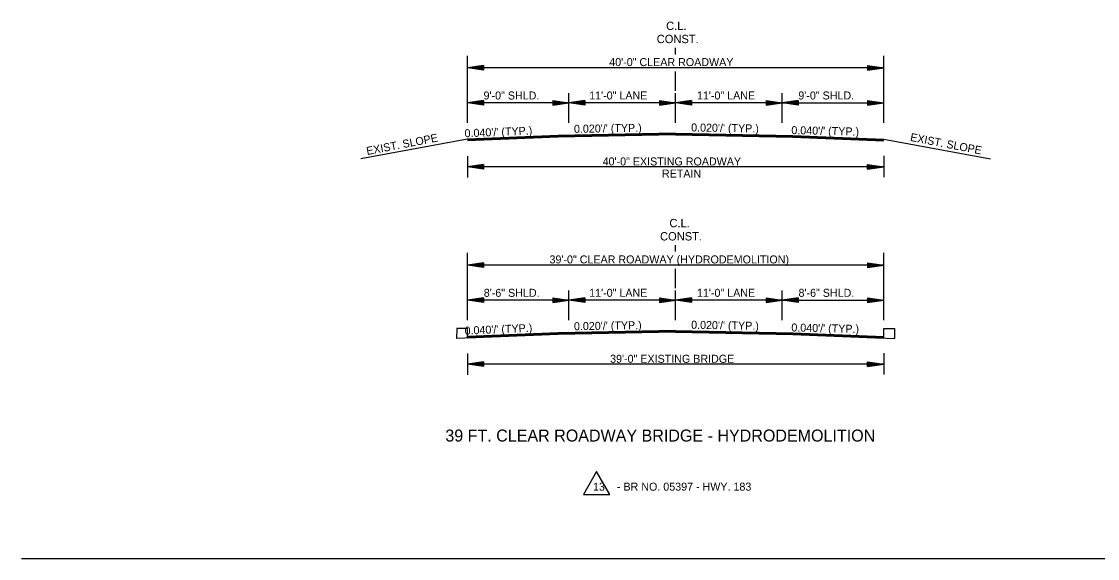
# Model space of a CAD drawing. Extents: x 549600 to 1930787, y -1955432 to 596640.
# Drawn here: x 551009 to 552017, y -1951238 to -1950735 of the extents above; entities that cross this region are included whole.
import ezdxf

# ---------------------------------------------------------------- set-up
doc = ezdxf.new("R2010")
doc.units = 0
doc.layers.add('R_Border', color=7, linetype='Continuous')
doc.layers.add('S_AREA_CALC', color=7, linetype='Continuous')

msp = doc.modelspace()

# ---------------------------------------------------------------- linework, layer by layer
at = {"layer": 'R_Border'}
for p, q in [((551512, -1950841.6), (551427, -1950845)), ((551512, -1950841.9), (551427, -1950845.3)), ((551512, -1950842.2), (551427, -1950845.6)), ((551512, -1950842.5), (551427, -1950845.9)), ((551512, -1950842.8), (551427, -1950846.2)), ((551512, -1950843.1), (551427, -1950846.5)), ((551512, -1950843.3), (551427, -1950846.7)), ((551732, -1950841.6), (551817, -1950845)), ((551732, -1950841.9), (551817, -1950845.3)), ((551732, -1950842.2), (551817, -1950845.6)), ((551732, -1950842.5), (551817, -1950845.9)), ((551732, -1950842.8), (551817, -1950846.2)), ((551732, -1950843.1), (551817, -1950846.5)), ((551732, -1950843.3), (551817, -1950846.7)), ((551416.9, -1951022.6), (551416.8, -1951031.9)), ((551512, -1951028.1), (551416.8, -1951031.9)), ((551427, -1951022.6), (551416.9, -1951022.6)), ((551427, -1951031.4), (551427, -1951022.6)), ((551512, -1951026.5), (551427, -1951029.9)), ((551512, -1951026.8), (551427, -1951030.2)), ((551512, -1951027.1), (551427, -1951030.5)), ((551512, -1951027.4), (551427, -1951030.8)), ((551512, -1951027.7), (551427, -1951031.1)), ((551512, -1951028), (551427, -1951031.4)), ((551732, -1951026.5), (551817, -1951029.9)), ((551732, -1951026.8), (551817, -1951030.2)), ((551732, -1951027.1), (551817, -1951030.5)), ((551732, -1951027.4), (551817, -1951030.8)), ((551732, -1951027.7), (551817, -1951031.1)), ((551732, -1951028), (551817, -1951031.4)), ((551732, -1951028.1), (551827.2, -1951031.9)), ((551817, -1951022.6), (551827.2, -1951022.6)), ((551817, -1951031.4), (551817, -1951022.6)), ((551827.2, -1951022.6), (551827.2, -1951031.9)), ((551535.6, -1951177.9), (551560.4, -1951177.9)), ((551009, -1951237.9), (552070.2, -1951237.9))]:
    msp.add_line(p, q, dxfattribs=at)
msp.add_lwpolyline([(551560.4, -1951177.9), (551548, -1951156.4), (551535.6, -1951177.9)], dxfattribs=at)
at = {"layer": 'S_AREA_CALC'}
for p, q in [((551622, -1950765.6), (551622, -1950759.4)), ((551427, -1950829.8), (551427, -1950766.9)), ((551817, -1950829.8), (551817, -1950766.9)), ((551442, -1950776), (551427, -1950778.2)), ((551817, -1950778.2), (551427, -1950778.2)), ((551442, -1950780.5), (551427, -1950778.2)), ((551442, -1950776.4), (551429.5, -1950778.2)), ((551442, -1950780.1), (551429.5, -1950778.2)), ((551442, -1950776.8), (551432.1, -1950778.2)), ((551442, -1950779.7), (551432.1, -1950778.2)), ((551442, -1950777.1), (551434.6, -1950778.2)), ((551442, -1950779.4), (551434.6, -1950778.2)), ((551442, -1950777.5), (551437.1, -1950778.2)), ((551442, -1950779), (551437.1, -1950778.2)), ((551442, -1950777.9), (551439.6, -1950778.2)), ((551442, -1950778.6), (551439.6, -1950778.2)), ((551442, -1950776), (551442, -1950780.5)), ((551802, -1950776), (551817, -1950778.2)), ((551802, -1950776), (551802, -1950780.5)), ((551802, -1950776.4), (551814.5, -1950778.2)), ((551802, -1950776.8), (551811.9, -1950778.2)), ((551802, -1950777.1), (551809.4, -1950778.2)), ((551802, -1950777.5), (551806.9, -1950778.2)), ((551802, -1950777.9), (551804.4, -1950778.2)), ((551802, -1950780.5), (551817, -1950778.2)), ((551802, -1950779), (551806.9, -1950778.2)), ((551802, -1950779.7), (551811.9, -1950778.2)), ((551802, -1950780.1), (551814.5, -1950778.2)), ((551802, -1950779.4), (551809.4, -1950778.2)), ((551802, -1950778.6), (551804.4, -1950778.2)), ((551622, -1950789.9), (551622, -1950781.6)), ((551622, -1950799.8), (551622, -1950789.9)), ((551442, -1950808.8), (551427, -1950811.1)), ((551442, -1950809.2), (551429.5, -1950811.1)), ((551442, -1950809.6), (551432.1, -1950811.1)), ((551442, -1950808.8), (551442, -1950813.3)), ((551507, -1950808.8), (551522, -1950811.1)), ((551507, -1950808.8), (551507, -1950813.3)), ((551507, -1950809.2), (551519.5, -1950811.1)), ((551507, -1950809.6), (551516.9, -1950811.1)), ((551522, -1950829.8), (551522, -1950801.9)), ((551537, -1950808.8), (551522, -1950811.1)), ((551537, -1950809.2), (551524.5, -1950811.1)), ((551537, -1950809.6), (551527.1, -1950811.1)), ((551537, -1950808.8), (551537, -1950813.3)), ((551607, -1950808.8), (551622, -1950811.1)), ((551607, -1950808.8), (551607, -1950813.3)), ((551607, -1950809.2), (551619.5, -1950811.1)), ((551607, -1950809.6), (551616.9, -1950811.1)), ((551622, -1950829.8), (551622, -1950801.9)), ((551637, -1950808.8), (551622, -1950811.1)), ((551637, -1950809.2), (551624.5, -1950811.1)), ((551637, -1950809.6), (551627.1, -1950811.1)), ((551637, -1950808.8), (551637, -1950813.3)), ((551707, -1950808.8), (551722, -1950811.1)), ((551707, -1950808.8), (551707, -1950813.3)), ((551707, -1950809.2), (551719.5, -1950811.1)), ((551707, -1950809.6), (551716.9, -1950811.1)), ((551722, -1950829.8), (551722, -1950801.9)), ((551737, -1950808.8), (551722, -1950811.1)), ((551737, -1950809.2), (551724.5, -1950811.1)), ((551737, -1950809.6), (551727.1, -1950811.1)), ((551737, -1950808.8), (551737, -1950813.3)), ((551802, -1950808.8), (551817, -1950811.1)), ((551802, -1950808.8), (551802, -1950813.3)), ((551802, -1950809.2), (551814.5, -1950811.1)), ((551802, -1950809.6), (551811.9, -1950811.1)), ((551522, -1950811.1), (551427, -1950811.1)), ((551442, -1950813.3), (551427, -1950811.1)), ((551442, -1950813), (551429.5, -1950811.1)), ((551442, -1950812.6), (551432.1, -1950811.1)), ((551442, -1950810), (551434.6, -1950811.1)), ((551442, -1950812.2), (551434.6, -1950811.1)), ((551442, -1950810.3), (551437.1, -1950811.1)), ((551442, -1950811.8), (551437.1, -1950811.1)), ((551442, -1950810.7), (551439.6, -1950811.1)), ((551442, -1950811.4), (551439.6, -1950811.1)), ((551507, -1950810), (551514.4, -1950811.1)), ((551507, -1950810.3), (551511.9, -1950811.1)), ((551507, -1950810.7), (551509.4, -1950811.1)), ((551507, -1950813.3), (551522, -1950811.1)), ((551507, -1950811.8), (551511.9, -1950811.1)), ((551507, -1950812.6), (551516.9, -1950811.1)), ((551507, -1950813), (551519.5, -1950811.1)), ((551507, -1950812.2), (551514.4, -1950811.1)), ((551507, -1950811.4), (551509.4, -1950811.1)), ((551622, -1950811.1), (551522, -1950811.1)), ((551537, -1950813.3), (551522, -1950811.1)), ((551537, -1950813), (551524.5, -1950811.1)), ((551537, -1950812.6), (551527.1, -1950811.1)), ((551537, -1950810), (551529.6, -1950811.1)), ((551537, -1950812.2), (551529.6, -1950811.1)), ((551537, -1950810.3), (551532.1, -1950811.1)), ((551537, -1950811.8), (551532.1, -1950811.1)), ((551537, -1950810.7), (551534.6, -1950811.1)), ((551537, -1950811.4), (551534.6, -1950811.1)), ((551607, -1950810), (551614.4, -1950811.1)), ((551607, -1950810.3), (551611.9, -1950811.1)), ((551607, -1950810.7), (551609.4, -1950811.1)), ((551607, -1950813.3), (551622, -1950811.1)), ((551607, -1950811.8), (551611.9, -1950811.1)), ((551607, -1950812.6), (551616.9, -1950811.1)), ((551607, -1950813), (551619.5, -1950811.1)), ((551607, -1950812.2), (551614.4, -1950811.1)), ((551607, -1950811.4), (551609.4, -1950811.1)), ((551722, -1950811.1), (551622, -1950811.1)), ((551637, -1950813.3), (551622, -1950811.1)), ((551637, -1950813), (551624.5, -1950811.1)), ((551637, -1950812.6), (551627.1, -1950811.1)), ((551637, -1950810), (551629.6, -1950811.1)), ((551637, -1950812.2), (551629.6, -1950811.1)), ((551637, -1950810.3), (551632.1, -1950811.1)), ((551637, -1950811.8), (551632.1, -1950811.1)), ((551637, -1950810.7), (551634.6, -1950811.1)), ((551637, -1950811.4), (551634.6, -1950811.1)), ((551707, -1950810), (551714.4, -1950811.1)), ((551707, -1950810.3), (551711.9, -1950811.1)), ((551707, -1950810.7), (551709.4, -1950811.1)), ((551707, -1950813.3), (551722, -1950811.1)), ((551707, -1950811.8), (551711.9, -1950811.1)), ((551707, -1950812.6), (551716.9, -1950811.1)), ((551707, -1950813), (551719.5, -1950811.1)), ((551707, -1950812.2), (551714.4, -1950811.1)), ((551707, -1950811.4), (551709.4, -1950811.1)), ((551722, -1950811.1), (551817, -1950811.1)), ((551737, -1950813.3), (551722, -1950811.1)), ((551737, -1950813), (551724.5, -1950811.1)), ((551737, -1950812.6), (551727.1, -1950811.1)), ((551737, -1950810), (551729.6, -1950811.1)), ((551737, -1950812.2), (551729.6, -1950811.1)), ((551737, -1950810.3), (551732.1, -1950811.1)), ((551737, -1950811.8), (551732.1, -1950811.1)), ((551737, -1950810.7), (551734.6, -1950811.1)), ((551737, -1950811.4), (551734.6, -1950811.1)), ((551802, -1950810), (551809.4, -1950811.1)), ((551802, -1950810.3), (551806.9, -1950811.1)), ((551802, -1950810.7), (551804.4, -1950811.1)), ((551802, -1950813.3), (551817, -1950811.1)), ((551802, -1950811.8), (551806.9, -1950811.1)), ((551802, -1950812.6), (551811.9, -1950811.1)), ((551802, -1950813), (551814.5, -1950811.1)), ((551802, -1950812.2), (551809.4, -1950811.1)), ((551802, -1950811.4), (551804.4, -1950811.1)), ((551622, -1950839.4), (551512, -1950841.6)), ((551622, -1950839.7), (551512, -1950841.9)), ((551622, -1950840), (551512, -1950842.2)), ((551622, -1950839.4), (551732, -1950841.6)), ((551622, -1950839.7), (551732, -1950841.9)), ((551622, -1950840), (551732, -1950842.2)), ((551427, -1950845), (551326.9, -1950863.4)), ((551622, -1950840.3), (551512, -1950842.5)), ((551622, -1950840.6), (551512, -1950842.8)), ((551622, -1950840.9), (551512, -1950843.1)), ((551622, -1950841.1), (551512, -1950843.3)), ((551622, -1950840.3), (551732, -1950842.5)), ((551622, -1950840.6), (551732, -1950842.8)), ((551622, -1950840.9), (551732, -1950843.1)), ((551622, -1950841.1), (551732, -1950843.3)), ((551817, -1950845), (551917.1, -1950863.4)), ((551427, -1950861), (551427, -1950881)), ((551442, -1950868.8), (551427, -1950871)), ((551442, -1950869.2), (551429.5, -1950871)), ((551442, -1950869.6), (551432.1, -1950871)), ((551442, -1950869.9), (551434.6, -1950871)), ((551442, -1950870.3), (551437.1, -1950871)), ((551442, -1950868.8), (551442, -1950873.3)), ((551802, -1950868.8), (551817, -1950871)), ((551802, -1950873.3), (551802, -1950868.8)), ((551802, -1950869.2), (551814.5, -1950871)), ((551802, -1950869.6), (551811.9, -1950871)), ((551802, -1950869.9), (551809.4, -1950871)), ((551802, -1950870.3), (551806.9, -1950871)), ((551817, -1950860.8), (551817, -1950880.8)), ((551442, -1950873.3), (551427, -1950871)), ((551817, -1950871), (551427, -1950871)), ((551442, -1950872.9), (551429.5, -1950871)), ((551442, -1950872.5), (551432.1, -1950871)), ((551442, -1950872.2), (551434.6, -1950871)), ((551442, -1950871.8), (551437.1, -1950871)), ((551442, -1950870.7), (551439.6, -1950871)), ((551442, -1950871.4), (551439.6, -1950871)), ((551802, -1950870.7), (551804.4, -1950871)), ((551802, -1950873.3), (551817, -1950871)), ((551802, -1950871.8), (551806.9, -1950871)), ((551802, -1950872.5), (551811.9, -1950871)), ((551802, -1950872.9), (551814.5, -1950871)), ((551802, -1950872.2), (551809.4, -1950871)), ((551802, -1950871.4), (551804.4, -1950871)), ((551622, -1950950.4), (551622, -1950944.3)), ((551427, -1951014.7), (551427, -1950951.7)), ((551442, -1950960.9), (551427, -1950963.1)), ((551442, -1950960.9), (551442, -1950965.4)), ((551802, -1950960.9), (551817, -1950963.1)), ((551802, -1950960.9), (551802, -1950965.4)), ((551817, -1951014.7), (551817, -1950951.7)), ((551817, -1950963.1), (551427, -1950963.1)), ((551442, -1950965.4), (551427, -1950963.1)), ((551442, -1950961.3), (551429.5, -1950963.1)), ((551442, -1950965), (551429.5, -1950963.1)), ((551442, -1950961.6), (551432.1, -1950963.1)), ((551442, -1950964.6), (551432.1, -1950963.1)), ((551442, -1950962), (551434.6, -1950963.1)), ((551442, -1950964.2), (551434.6, -1950963.1)), ((551442, -1950962.4), (551437.1, -1950963.1)), ((551442, -1950963.9), (551437.1, -1950963.1)), ((551442, -1950962.8), (551439.6, -1950963.1)), ((551442, -1950963.5), (551439.6, -1950963.1)), ((551622, -1950974.8), (551622, -1950966.5)), ((551802, -1950961.3), (551814.5, -1950963.1)), ((551802, -1950961.6), (551811.9, -1950963.1)), ((551802, -1950962), (551809.4, -1950963.1)), ((551802, -1950962.4), (551806.9, -1950963.1)), ((551802, -1950962.8), (551804.4, -1950963.1)), ((551802, -1950965.4), (551817, -1950963.1)), ((551802, -1950963.9), (551806.9, -1950963.1)), ((551802, -1950964.6), (551811.9, -1950963.1)), ((551802, -1950965), (551814.5, -1950963.1)), ((551802, -1950964.2), (551809.4, -1950963.1)), ((551802, -1950963.5), (551804.4, -1950963.1)), ((551622, -1950984.6), (551622, -1950974.8)), ((551522, -1951014.7), (551522, -1950986.8)), ((551622, -1951014.7), (551622, -1950986.8)), ((551722, -1951014.7), (551722, -1950986.8)), ((551442, -1950993.7), (551427, -1950996)), ((551522, -1950996), (551427, -1950996)), ((551442, -1950998.2), (551427, -1950996)), ((551442, -1950994.1), (551429.5, -1950996)), ((551442, -1950997.8), (551429.5, -1950996)), ((551442, -1950994.5), (551432.1, -1950996)), ((551442, -1950997.5), (551432.1, -1950996)), ((551442, -1950994.8), (551434.6, -1950996)), ((551442, -1950997.1), (551434.6, -1950996)), ((551442, -1950995.2), (551437.1, -1950996)), ((551442, -1950996.7), (551437.1, -1950996)), ((551442, -1950995.6), (551439.6, -1950996)), ((551442, -1950996.3), (551439.6, -1950996)), ((551442, -1950993.7), (551442, -1950998.2)), ((551507, -1950993.7), (551522, -1950996)), ((551507, -1950993.7), (551507, -1950998.2)), ((551507, -1950994.1), (551519.5, -1950996)), ((551507, -1950994.5), (551516.9, -1950996)), ((551507, -1950994.8), (551514.4, -1950996)), ((551507, -1950995.2), (551511.9, -1950996)), ((551507, -1950995.6), (551509.4, -1950996)), ((551507, -1950998.2), (551522, -1950996)), ((551507, -1950996.7), (551511.9, -1950996)), ((551507, -1950997.5), (551516.9, -1950996)), ((551507, -1950997.8), (551519.5, -1950996)), ((551507, -1950997.1), (551514.4, -1950996)), ((551507, -1950996.3), (551509.4, -1950996)), ((551537, -1950993.7), (551522, -1950996)), ((551622, -1950996), (551522, -1950996)), ((551537, -1950998.2), (551522, -1950996)), ((551537, -1950994.1), (551524.5, -1950996)), ((551537, -1950997.8), (551524.5, -1950996)), ((551537, -1950994.5), (551527.1, -1950996)), ((551537, -1950997.5), (551527.1, -1950996)), ((551537, -1950994.8), (551529.6, -1950996)), ((551537, -1950997.1), (551529.6, -1950996)), ((551537, -1950995.2), (551532.1, -1950996)), ((551537, -1950996.7), (551532.1, -1950996)), ((551537, -1950995.6), (551534.6, -1950996)), ((551537, -1950996.3), (551534.6, -1950996)), ((551537, -1950993.7), (551537, -1950998.2)), ((551607, -1950993.7), (551622, -1950996)), ((551607, -1950993.7), (551607, -1950998.2)), ((551607, -1950994.1), (551619.5, -1950996)), ((551607, -1950994.5), (551616.9, -1950996)), ((551607, -1950994.8), (551614.4, -1950996)), ((551607, -1950995.2), (551611.9, -1950996)), ((551607, -1950995.6), (551609.4, -1950996)), ((551607, -1950998.2), (551622, -1950996)), ((551607, -1950996.7), (551611.9, -1950996)), ((551607, -1950997.5), (551616.9, -1950996)), ((551607, -1950997.8), (551619.5, -1950996)), ((551607, -1950997.1), (551614.4, -1950996)), ((551607, -1950996.3), (551609.4, -1950996)), ((551637, -1950993.7), (551622, -1950996)), ((551722, -1950996), (551622, -1950996)), ((551637, -1950998.2), (551622, -1950996)), ((551637, -1950994.1), (551624.5, -1950996)), ((551637, -1950997.8), (551624.5, -1950996)), ((551637, -1950994.5), (551627.1, -1950996)), ((551637, -1950997.5), (551627.1, -1950996)), ((551637, -1950994.8), (551629.6, -1950996)), ((551637, -1950997.1), (551629.6, -1950996)), ((551637, -1950995.2), (551632.1, -1950996)), ((551637, -1950996.7), (551632.1, -1950996)), ((551637, -1950995.6), (551634.6, -1950996)), ((551637, -1950996.3), (551634.6, -1950996)), ((551637, -1950993.7), (551637, -1950998.2)), ((551707, -1950993.7), (551722, -1950996)), ((551707, -1950993.7), (551707, -1950998.2)), ((551707, -1950994.1), (551719.5, -1950996)), ((551707, -1950994.5), (551716.9, -1950996)), ((551707, -1950994.8), (551714.4, -1950996)), ((551707, -1950995.2), (551711.9, -1950996)), ((551707, -1950995.6), (551709.4, -1950996)), ((551707, -1950998.2), (551722, -1950996)), ((551707, -1950996.7), (551711.9, -1950996)), ((551707, -1950997.5), (551716.9, -1950996)), ((551707, -1950997.8), (551719.5, -1950996)), ((551707, -1950997.1), (551714.4, -1950996)), ((551707, -1950996.3), (551709.4, -1950996)), ((551737, -1950993.7), (551722, -1950996)), ((551722, -1950996), (551817, -1950996)), ((551737, -1950998.2), (551722, -1950996)), ((551737, -1950994.1), (551724.5, -1950996)), ((551737, -1950997.8), (551724.5, -1950996)), ((551737, -1950994.5), (551727.1, -1950996)), ((551737, -1950997.5), (551727.1, -1950996)), ((551737, -1950994.8), (551729.6, -1950996)), ((551737, -1950997.1), (551729.6, -1950996)), ((551737, -1950995.2), (551732.1, -1950996)), ((551737, -1950996.7), (551732.1, -1950996)), ((551737, -1950995.6), (551734.6, -1950996)), ((551737, -1950996.3), (551734.6, -1950996)), ((551737, -1950993.7), (551737, -1950998.2)), ((551802, -1950993.7), (551817, -1950996)), ((551802, -1950993.7), (551802, -1950998.2)), ((551802, -1950994.1), (551814.5, -1950996)), ((551802, -1950994.5), (551811.9, -1950996)), ((551802, -1950994.8), (551809.4, -1950996)), ((551802, -1950995.2), (551806.9, -1950996)), ((551802, -1950995.6), (551804.4, -1950996)), ((551802, -1950998.2), (551817, -1950996)), ((551802, -1950996.7), (551806.9, -1950996)), ((551802, -1950997.5), (551811.9, -1950996)), ((551802, -1950997.8), (551814.5, -1950996)), ((551802, -1950997.1), (551809.4, -1950996)), ((551802, -1950996.3), (551804.4, -1950996)), ((551622, -1951024.3), (551512, -1951026.5)), ((551622, -1951024.6), (551512, -1951026.8)), ((551622, -1951024.9), (551512, -1951027.1)), ((551622, -1951025.2), (551512, -1951027.4)), ((551622, -1951025.5), (551512, -1951027.7)), ((551622, -1951025.8), (551512, -1951028)), ((551622, -1951025.9), (551512, -1951028.1)), ((551622, -1951024.3), (551732, -1951026.5)), ((551622, -1951024.6), (551732, -1951026.8)), ((551622, -1951024.9), (551732, -1951027.1)), ((551622, -1951025.2), (551732, -1951027.4)), ((551622, -1951025.5), (551732, -1951027.7)), ((551622, -1951025.8), (551732, -1951028)), ((551622, -1951025.9), (551732, -1951028.1)), ((551427, -1951045.9), (551427, -1951065.9)), ((551817, -1951045.7), (551817, -1951065.7)), ((551442, -1951053.7), (551427, -1951055.9)), ((551442, -1951058.2), (551427, -1951055.9)), ((551817, -1951055.9), (551427, -1951055.9)), ((551442, -1951054.1), (551429.5, -1951055.9)), ((551442, -1951057.8), (551429.5, -1951055.9)), ((551442, -1951054.4), (551432.1, -1951055.9)), ((551442, -1951057.4), (551432.1, -1951055.9)), ((551442, -1951054.8), (551434.6, -1951055.9)), ((551442, -1951057), (551434.6, -1951055.9)), ((551442, -1951055.2), (551437.1, -1951055.9)), ((551442, -1951056.7), (551437.1, -1951055.9)), ((551442, -1951055.6), (551439.6, -1951055.9)), ((551442, -1951056.3), (551439.6, -1951055.9)), ((551442, -1951053.7), (551442, -1951058.2)), ((551802, -1951053.7), (551817, -1951055.9)), ((551802, -1951058.2), (551802, -1951053.7)), ((551802, -1951054.1), (551814.5, -1951055.9)), ((551802, -1951054.4), (551811.9, -1951055.9)), ((551802, -1951054.8), (551809.4, -1951055.9)), ((551802, -1951055.2), (551806.9, -1951055.9)), ((551802, -1951055.6), (551804.4, -1951055.9)), ((551802, -1951058.2), (551817, -1951055.9)), ((551802, -1951056.7), (551806.9, -1951055.9)), ((551802, -1951057.4), (551811.9, -1951055.9)), ((551802, -1951057.8), (551814.5, -1951055.9)), ((551802, -1951057), (551809.4, -1951055.9)), ((551802, -1951056.3), (551804.4, -1951055.9))]:
    msp.add_line(p, q, dxfattribs=at)

# ---------------------------------------------------------------- texts
at = {"layer": 'R_Border'}
for s, p in [('13', (551544.6, -1951174.4)), ('- BR NO. 05397 - HWY. 183', (551567, -1951174.4))]:
    msp.add_text(s, height=7.5, dxfattribs=at).set_placement(p)
at = {"layer": 'S_AREA_CALC'}
for s, height, p in [('C.L.', 7.8, (551613.1, -1950742.8)), ('CONST.', 7.8, (551604.3, -1950755.1)), ('40\'-0" CLEAR ROADWAY', 7.5, (551559.8, -1950776.6)), ('9\'-0" SHLD.', 7.5, (551442, -1950807.9)), ('11\'-0" LANE', 7.5, (551541, -1950807.9)), ('11\'-0" LANE', 7.5, (551642, -1950807.9)), ('9\'-0" SHLD.', 7.5, (551737, -1950807.9)), ('40\'-0" EXISTING ROADWAY', 7.5, (551553.6, -1950869.7)), ('RETAIN', 7.5, (551609.2, -1950881.1)), ('C.L.', 7.8, (551616.2, -1950927.6)), ('CONST.', 7.8, (551607.4, -1950940)), ('39\'-0" CLEAR ROADWAY (HYDRODEMOLITION)', 7.5, (551503.8, -1950961.5)), ('8\'-6" SHLD.', 7.5, (551442.2, -1950992.8)), ('11\'-0" LANE', 7.5, (551541, -1950992.8)), ('11\'-0" LANE', 7.5, (551642, -1950992.8)), ('8\'-6" SHLD.', 7.5, (551737.2, -1950992.8)), ('39\'-0" EXISTING BRIDGE', 7.5, (551560.6, -1951054.6)), ('39 FT. CLEAR ROADWAY BRIDGE - HYDRODEMOLITION', 11.25, (551406.2, -1951128.4))]:
    msp.add_text(s, height=height, dxfattribs=at).set_placement(p)
for s, rotation, p in [('EXIST. SLOPE', 10.8829, (551332.9, -1950860)), ("  0.040'/' (TYP.)", 2.448, (551418.8, -1950843.6)), ("0.020'/' (TYP.)", 0.9719, (551526.8, -1950839.2)), ("0.020'/' (TYP.)", 359.0281, (551636.5, -1950837.8)), ("0.040'/' (TYP.)", 358.6816, (551730.4, -1950840.3)), ('EXIST. SLOPE', 349.1171, (551841.4, -1950846.6)), ("  0.040'/' (TYP.)", 2.448, (551418.8, -1951028.5)), ("0.020'/' (TYP.)", 0.9719, (551526.8, -1951024.1)), ("0.020'/' (TYP.)", 359.0281, (551636.5, -1951022.7)), ("0.040'/' (TYP.)", 358.6816, (551730.4, -1951025.2))]:
    msp.add_text(s, height=7.5, rotation=rotation, dxfattribs=at).set_placement(p)

doc.saveas('drawing.dxf')
